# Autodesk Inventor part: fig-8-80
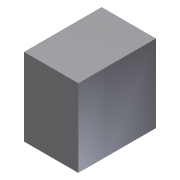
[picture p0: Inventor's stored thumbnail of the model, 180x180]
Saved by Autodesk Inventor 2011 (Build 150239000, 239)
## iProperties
Created: 2009-04
Part Number: fig-8-80
Document SubType Name: Modeling
Designer: Sham
Density: 1 g/cm^3
Author: Sham
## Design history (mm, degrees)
sketch "Sketch5"
  geometry: L1 (14, -20)-(0, -20); L2 (0, -20)-(0, 0); L3 (0, 0)-(14, 0); L4 (14, 0)-(14, -20)
  constraints: 8 end point
extrude "Extrusion2" new body sketch "Sketch5" distance "d3" = 20; taper "d4" = 0 deg
sketch "Sketch6"
  geometry: L1 (-5, 12)-(17, 7)
  constraints: 2 end point
split "Split8" sketch "Sketch6"
  body "Solid2"
body "Solid3"
body "Solid4"
